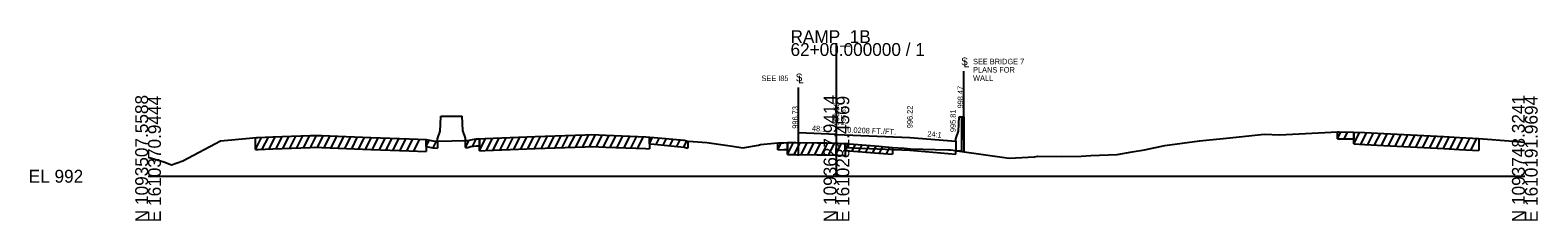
# Model space of a CAD drawing. Extents: x -26 to 1615461, y 490 to 1281970.
# Drawn here: x -25.7 to 302.8, y 6490.3 to 6531.8 of the extents above; entities that cross this region are included whole.
import ezdxf

# ---------------------------------------------------------------- set-up
doc = ezdxf.new("R2010")
doc.units = 0
for name, color, linetype in [('RD_EX_Misc', 7, 'Continuous'), ('RD_GPK_XS_Cell', 7, 'Continuous'), ('RD_Sketch1', 7, 'Continuous'), ('RD_XE_Ground', 7, 'Continuous'), ('RD_XS_Base', 7, 'Continuous'), ('RD_XS_CurbFront', 7, 'Continuous'), ('RD_XS_ExGround', 7, 'Continuous'), ('RD_XS_ExPaveRet', 7, 'Continuous'), ('RD_XS_MatchLine', 7, 'Continuous'), ('RD_XS_MedBbase', 7, 'Continuous'), ('RD_XS_MedBWall', 7, 'Continuous'), ('RD_XS_Pave', 7, 'Continuous'), ('RD_XS_PaveShd', 7, 'Continuous'), ('RD_XS_TX_Elev_EX', 7, 'Continuous'), ('RD_XS_TX_Elev_PR', 7, 'Continuous'), ('RD_XS_TX_MatchLine', 7, 'Continuous'), ('RD_XS_TX_Notes', 7, 'Continuous'), ('RD_XS_TX_ShdSlope', 7, 'Continuous'), ('RD_XS_TX_Slope', 7, 'Continuous')]:
    doc.layers.add(name, color=color, linetype=linetype)

msp = doc.modelspace()

# ---------------------------------------------------------------- linework, layer by layer
at = {"layer": 'RD_EX_Misc'}
for p, q in [((109.23, 6507.04), (109.23, 6508.54)), ((259.17, 6508.16), (259.17, 6509.66)), ((262.77, 6509.62), (262.77, 6508.12)), ((60.59, 6506.48), (60.59, 6507.98)), ((60.59, 6506.48), (62.08, 6506.18)), ((62.08, 6506.18), (63.08, 6506.13)), ((63.08, 6507.63), (63.08, 6506.13)), ((69.17, 6506.27), (69.17, 6507.77)), ((69.17, 6506.27), (69.71, 6506.25)), ((69.71, 6506.25), (70.34, 6506.44)), ((70.34, 6506.44), (71.52, 6506.61)), ((71.52, 6506.61), (72.22, 6506.65)), ((72.22, 6508.15), (72.22, 6506.65)), ((109.23, 6507.04), (110.25, 6506.95)), ((110.25, 6506.95), (116.8, 6506.32)), ((116.8, 6506.32), (117.59, 6506.12)), ((117.59, 6507.62), (117.59, 6506.12)), ((137.2, 6505.76), (137.2, 6507.26)), ((137.2, 6505.76), (138.57, 6505.8)), ((138.57, 6505.8), (139.32, 6505.81)), ((139.32, 6507.31), (139.32, 6505.81)), ((151.91, 6505.62), (151.91, 6507.12)), ((151.91, 6505.62), (159.26, 6505.03)), ((159.26, 6505.03), (162.25, 6504.79)), ((162.25, 6506.29), (162.25, 6504.79)), ((259.17, 6508.16), (259.18, 6508.16)), ((259.18, 6508.16), (259.58, 6508.15)), ((259.58, 6508.15), (262.77, 6508.12)), ((262.77, 6508.12), (262.77, 6508.12))]:
    msp.add_line(p, q, dxfattribs=at)
at = {"layer": 'RD_GPK_XS_Cell'}
for p, q in [((150, 6500), (150, 6528.98)), ((0, 6500), (150, 6500)), ((150, 6500), (300, 6500))]:
    msp.add_line(p, q, dxfattribs=at)
at = {"layer": 'RD_Sketch1'}
for p, q in [((109.23, 6507.04), (109.95, 6508.48)), ((110.73, 6506.9), (111.45, 6508.33)), ((259.17, 6508.16), (259.92, 6509.65)), ((260.67, 6508.14), (261.42, 6509.63)), ((60.59, 6506.48), (61.27, 6507.84)), ((62.09, 6506.18), (62.82, 6507.64)), ((69.17, 6506.27), (69.95, 6507.82)), ((70.67, 6506.49), (71.48, 6508.1)), ((112.23, 6506.76), (112.95, 6508.19)), ((113.73, 6506.61), (114.45, 6508.04)), ((115.23, 6506.47), (115.95, 6507.9)), ((116.73, 6506.32), (117.4, 6507.67)), ((137.2, 6505.76), (137.97, 6507.28)), ((151.91, 6505.62), (152.63, 6507.06)), ((153.41, 6505.5), (154.13, 6506.94)), ((154.91, 6505.38), (155.63, 6506.82)), ((156.41, 6505.26), (157.13, 6506.7)), ((157.91, 6505.14), (158.63, 6506.58)), ((159.41, 6505.02), (160.13, 6506.46)), ((160.91, 6504.9), (161.63, 6506.34))]:
    msp.add_line(p, q, dxfattribs=at)
at = {"layer": 'RD_XE_Ground'}
for p, q in [((63.66, 6509.8), (63.83, 6512.96)), ((63.83, 6513.1), (68.42, 6513.1)), ((63.83, 6512.96), (63.83, 6513.1)), ((68.59, 6509.94), (68.42, 6513.1)), ((63.08, 6508.13), (63.66, 6509.8)), ((69.17, 6508.27), (68.59, 6509.94)), ((69.17, 6507.77), (69.17, 6508.27)), ((63.08, 6507.63), (63.08, 6508.13))]:
    msp.add_line(p, q, dxfattribs=at)
at = {"layer": 'RD_XS_Base'}
for p, q in [((141.71, 6507.31), (145.82, 6507.29)), ((145.82, 6507.29), (147.9, 6507.24)), ((147.9, 6507.24), (150, 6507.21)), ((150, 6507.21), (150.36, 6507.21)), ((150.36, 6507.21), (151.36, 6507.14)), ((151.36, 6507.14), (151.91, 6507.12)), ((151.91, 6507.12), (151.91, 6506.25)), ((151.91, 6506.25), (166, 6505.67)), ((166, 6505.67), (176, 6504.83)), ((176, 6504.83), (176, 6505.48))]:
    msp.add_line(p, q, dxfattribs=at)
at = {"layer": 'RD_XS_CurbFront'}
for p, q in [((177.25, 6512.94), (177.25, 6512.28)), ((176, 6507.61), (176, 6505.48))]:
    msp.add_line(p, q, dxfattribs=at)
at = {"layer": 'RD_XS_ExGround'}
msp.add_lwpolyline([(0, 6504.15), (3.44, 6503.14), (5.11, 6502.45), (7.61, 6503.39), (15.75, 6507.71), (18.17, 6507.94), (23.63, 6508.42), (23.98, 6508.43), (25.54, 6508.49), (27.18, 6508.55), (35.33, 6508.87), (36.23, 6508.9), (37.87, 6508.84), (48.56, 6508.44), (56.92, 6508.12), (60.59, 6507.98), (62.08, 6507.68), (63.22, 6507.62), (66.18, 6507.71), (69.16, 6507.77), (69.71, 6507.75), (70.34, 6507.94), (71.52, 6508.11), (72.24, 6508.15), (73.46, 6508.21), (84.38, 6508.64), (95.27, 6509.03), (96.68, 6509.08), (99.78, 6508.96), (108.45, 6508.61), (110.25, 6508.45), (116.8, 6507.82), (117.59, 6507.62), (118.78, 6507.57), (121.77, 6507.37), (127.32, 6506.57), (129.59, 6506.18), (133.05, 6506.76), (133.47, 6506.88), (134.18, 6506.96), (137.2, 6507.26), (138.57, 6507.3), (139.32, 6507.31), (141.14, 6507.31), (145.82, 6507.29), (147.9, 6507.24), (150, 6507.21), (150.36, 6507.21), (151.36, 6507.14), (151.91, 6507.12), (159.26, 6506.53), (162.25, 6506.29), (164.75, 6506.08), (165.47, 6506.01), (166.11, 6505.97), (171.5, 6505.85), (174.43, 6505.77), (174.91, 6505.74), (176.82, 6505.49), (187.64, 6503.93), (193.17, 6504.23), (193.85, 6504.36), (199.14, 6504.31), (203.3, 6504.39), (205.43, 6504.54), (211.16, 6504.74), (214.47, 6505.28), (217.1, 6505.75), (221.54, 6506.68), (229.08, 6507.72), (234.97, 6508.28), (239.87, 6508.81), (243.24, 6509.14), (246.65, 6509.03), (259.18, 6509.66), (259.58, 6509.65), (262.77, 6509.62), (265.12, 6509.52), (269.3, 6509.29), (282.36, 6508.65), (285.75, 6508.45), (289.96, 6508.19), (297.43, 6507.6), (298.23, 6507.53), (300, 6507.39)], dxfattribs=at)
at = {"layer": 'RD_XS_ExPaveRet'}
for p, q in [((23.4, 6505.8), (24.73, 6508.46)), ((23.4, 6505.8), (23.4, 6508.4)), ((24.9, 6505.87), (26.22, 6508.51)), ((26.4, 6505.92), (27.72, 6508.57)), ((27.9, 6505.97), (29.22, 6508.63)), ((29.4, 6506.03), (30.72, 6508.69)), ((30.9, 6506.09), (32.22, 6508.75)), ((32.4, 6506.15), (33.72, 6508.8)), ((33.9, 6506.21), (35.22, 6508.86)), ((35.4, 6506.27), (36.71, 6508.89)), ((36.9, 6506.28), (38.17, 6508.83)), ((38.4, 6506.22), (39.67, 6508.78)), ((39.9, 6506.17), (41.17, 6508.72)), ((41.4, 6506.11), (42.67, 6508.66)), ((42.9, 6506.06), (44.17, 6508.61)), ((44.4, 6506), (45.67, 6508.55)), ((45.9, 6505.94), (47.17, 6508.5)), ((47.4, 6505.89), (48.67, 6508.44)), ((48.9, 6505.83), (50.17, 6508.38)), ((50.4, 6505.77), (51.67, 6508.32)), ((51.9, 6505.72), (53.17, 6508.27)), ((73.72, 6505.62), (75.04, 6508.27)), ((75.22, 6505.68), (76.54, 6508.33)), ((76.72, 6505.74), (78.04, 6508.39)), ((78.22, 6505.8), (79.54, 6508.45)), ((79.72, 6505.85), (81.04, 6508.51)), ((81.22, 6505.91), (82.54, 6508.57)), ((82.72, 6505.97), (84.04, 6508.63)), ((84.22, 6506.03), (85.54, 6508.68)), ((85.72, 6506.09), (87.04, 6508.74)), ((87.22, 6506.14), (88.54, 6508.79)), ((88.72, 6506.2), (90.04, 6508.84)), ((90.22, 6506.25), (91.54, 6508.9)), ((91.72, 6506.3), (93.04, 6508.95)), ((93.22, 6506.36), (94.54, 6509.01)), ((94.72, 6506.41), (96.04, 6509.06)), ((96.22, 6506.46), (97.51, 6509.04)), ((97.72, 6506.44), (98.99, 6508.99)), ((99.22, 6506.38), (100.49, 6508.93)), ((100.72, 6506.32), (101.99, 6508.87)), ((102.22, 6506.26), (103.49, 6508.81)), ((103.72, 6506.2), (104.99, 6508.75)), ((105.22, 6506.14), (106.49, 6508.69)), ((106.72, 6506.08), (107.99, 6508.63)), ((109.23, 6508.54), (109.23, 6505.94)), ((262.77, 6507.02), (262.77, 6509.62)), ((262.77, 6507.02), (264.04, 6509.56)), ((264.27, 6506.95), (265.54, 6509.49)), ((265.77, 6506.88), (267.04, 6509.41)), ((267.27, 6506.8), (268.54, 6509.33)), ((268.77, 6506.72), (270.04, 6509.26)), ((270.27, 6506.64), (271.54, 6509.18)), ((271.77, 6506.57), (273.04, 6509.11)), ((273.27, 6506.5), (274.54, 6509.03)), ((274.77, 6506.42), (276.04, 6508.96)), ((276.27, 6506.35), (277.54, 6508.88)), ((277.77, 6506.27), (279.04, 6508.81)), ((279.27, 6506.2), (280.54, 6508.74)), ((280.77, 6506.13), (282.04, 6508.66)), ((282.27, 6506.05), (283.53, 6508.58)), ((283.77, 6505.97), (285.03, 6508.49)), ((285.27, 6505.88), (286.53, 6508.41)), ((286.77, 6505.79), (288.03, 6508.31)), ((23.4, 6505.8), (23.63, 6505.82)), ((23.63, 6505.82), (23.98, 6505.83)), ((23.98, 6505.83), (25.54, 6505.89)), ((25.54, 6505.89), (27.18, 6505.95)), ((27.18, 6505.95), (35.33, 6506.27)), ((35.33, 6506.27), (36.23, 6506.3)), ((36.23, 6506.3), (37.87, 6506.24)), ((37.87, 6506.24), (48.56, 6505.84)), ((48.56, 6505.84), (56.92, 6505.52)), ((53.4, 6505.66), (54.67, 6508.21)), ((54.9, 6505.6), (56.17, 6508.15)), ((56.4, 6505.54), (57.67, 6508.09)), ((56.92, 6505.52), (60.59, 6505.38)), ((57.9, 6505.48), (59.17, 6508.03)), ((60.59, 6507.98), (60.59, 6505.38)), ((72.22, 6505.55), (73.55, 6508.21)), ((72.22, 6505.55), (72.22, 6508.15)), ((72.22, 6505.55), (72.24, 6505.55)), ((72.24, 6505.55), (73.46, 6505.61)), ((73.46, 6505.61), (84.38, 6506.04)), ((84.38, 6506.04), (95.27, 6506.43)), ((95.27, 6506.43), (96.68, 6506.48)), ((96.68, 6506.48), (99.78, 6506.36)), ((99.78, 6506.36), (108.45, 6506.01)), ((108.45, 6506.01), (109.23, 6505.94)), ((139.32, 6504.71), (140.61, 6507.31)), ((139.32, 6504.71), (139.32, 6507.31)), ((140.82, 6504.71), (142.11, 6507.3)), ((142.32, 6504.7), (143.61, 6507.3)), ((143.82, 6504.7), (145.11, 6507.3)), ((145.32, 6504.7), (146.61, 6507.27)), ((146.82, 6504.67), (148.1, 6507.24)), ((148.32, 6504.64), (149.61, 6507.22)), ((149.82, 6504.62), (151.09, 6507.16)), ((151.91, 6507.12), (151.91, 6504.52)), ((262.77, 6507.02), (265.12, 6506.92)), ((265.12, 6506.92), (269.3, 6506.69)), ((269.3, 6506.69), (282.36, 6506.05)), ((282.36, 6506.05), (285.75, 6505.85)), ((285.75, 6505.85), (289.96, 6505.59)), ((288.27, 6505.7), (289.53, 6508.22)), ((289.96, 6508.19), (289.96, 6505.59)), ((289.96, 6505.59), (289.96, 6505.59)), ((139.32, 6504.71), (141.14, 6504.71)), ((141.14, 6504.71), (145.82, 6504.69)), ((145.82, 6504.69), (147.9, 6504.64)), ((147.9, 6504.64), (150, 6504.61)), ((150, 6504.61), (150.36, 6504.61)), ((150.36, 6504.61), (151.36, 6504.54)), ((151.36, 6504.54), (151.91, 6504.52))]:
    msp.add_line(p, q, dxfattribs=at)
at = {"layer": 'RD_XS_MatchLine'}
for p, q in [((177.75, 6512.94), (177.75, 6505.35)), ((141.71, 6507.31), (141.71, 6509.46))]:
    msp.add_line(p, q, dxfattribs=at)
at = {"layer": 'RD_XS_MedBbase'}
for p, q in [((177.75, 6512.28), (177.25, 6512.28)), ((177.25, 6512.28), (177.25, 6505.48)), ((177.75, 6512.94), (177.75, 6512.28)), ((177.25, 6505.48), (176, 6505.48))]:
    msp.add_line(p, q, dxfattribs=at)
at = {"layer": 'RD_XS_MedBWall'}
for p, q in [((176.58, 6509.78), (176.75, 6512.94)), ((176.75, 6512.94), (177.25, 6512.94)), ((177.25, 6512.94), (177.75, 6512.94)), ((176, 6508.11), (176.58, 6509.78)), ((176, 6507.61), (176, 6508.11))]:
    msp.add_line(p, q, dxfattribs=at)
at = {"layer": 'RD_XS_Pave'}
msp.add_line((150, 6509.11), (166, 6508.44), dxfattribs=at)
at = {"layer": 'RD_XS_PaveShd'}
for p, q in [((150, 6509.11), (141.71, 6509.46)), ((166, 6508.44), (176, 6507.61))]:
    msp.add_line(p, q, dxfattribs=at)
at = {"layer": 'RD_XS_TX_MatchLine'}
for p, q in [((177.75, 6512.94), (177.75, 6522.83)), ((141.71, 6509.46), (141.71, 6519.34)), ((177.75, 6507.94), (177.75, 6512.94)), ((141.71, 6504.46), (141.71, 6509.46))]:
    msp.add_line(p, q, dxfattribs=at)

# ---------------------------------------------------------------- texts
at = {"layer": 'RD_GPK_XS_Cell'}
for s, p in [('RAMP_1B', (140, 6528.98)), ('62+00.000000 / 1', (140, 6526.18)), ('EL 992', (-26, 6498.6))]:
    msp.add_text(s, height=2.8, dxfattribs=at).set_placement(p)
for s, p in [('N 1093507.5588', (0, 6490)), ('E 1610370.9444', (2.8, 6490)), ('N 1093627.9414', (150, 6490)), ('E 1610281.4569', (152.8, 6490)), ('N 1093748.3241', (300, 6490)), ('E 1610191.9694', (302.8, 6490))]:
    msp.add_text(s, height=2.8, rotation=90, dxfattribs=at).set_placement(p)
at = {"layer": 'RD_XS_TX_Elev_EX'}
msp.add_text('995.61', height=1, rotation=90, dxfattribs=at).set_placement((152, 6511.11))
at = {"layer": 'RD_XS_TX_Elev_PR'}
for s, p in [('998.47', (177.59, 6514.75)), ('996.73', (141.61, 6510.35)), ('996.56', (150.6, 6511.11)), ('996.22', (166.6, 6510.45)), ('995.81', (176, 6509.61))]:
    msp.add_text(s, height=1.2, rotation=90, dxfattribs=at).set_placement(p)
at = {"layer": 'RD_XS_TX_MatchLine'}
for s, p in [('S', (177.17, 6524.15)), ('L', (177.68, 6523.71)), ('S', (141.12, 6520.66)), ('L', (141.64, 6520.23))]:
    msp.add_text(s, height=1.68, dxfattribs=at).set_placement(p)
at = {"layer": 'RD_XS_TX_Notes'}
for s, p in [('SEE BRIDGE 7', (179.77, 6524.36)), ('WALL', (179.77, 6520.76)), ('PLANS FOR ', (179.77, 6522.56))]:
    msp.add_text(s, height=1.2, dxfattribs=at).set_placement(p)
msp.add_text('SEE I85', height=1.2, rotation=360, dxfattribs=at).set_placement((133.66, 6520.71))
at = {"layer": 'RD_XS_TX_ShdSlope'}
for s, rotation, p in [('48:1', 357.6141, (144.65, 6509.83)), ('24:1', 355.2364, (169.77, 6508.63))]:
    msp.add_text(s, height=1.2, rotation=rotation, dxfattribs=at).set_placement(p)
at = {"layer": 'RD_XS_TX_Slope'}
msp.add_text('0.0208 FT./FT.', height=1.2, rotation=357.6141, dxfattribs=at).set_placement((152.35, 6509.51))

doc.saveas('drawing.dxf')
